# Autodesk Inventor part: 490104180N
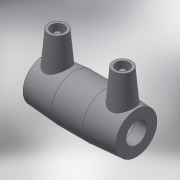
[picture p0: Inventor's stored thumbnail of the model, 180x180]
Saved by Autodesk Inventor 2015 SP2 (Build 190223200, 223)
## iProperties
Created: 2017-06
Part Number: 490104180N
Material: Generic
Description: PLASSON COUPLER 180-180
Document SubType Name: Modeling
Designer: KIM
Mass: 55.0731 g
Surface Area: 148.067 cm^2
Volume: 55.0731 cm^3
Density: 1 g/cm^3
Appearance: Default
Author: KIM
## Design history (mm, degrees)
derived "490104.ipt"
feature "Solid1::490104.ipt"
tag "TaggingFeature1"
body "Solid1"
other parameters: "d0" = 212, "d2" = 218, "d3" = 105, "d4" = 70.66667, "d5" = 196.2, "d6" = 171, "d8" = 168 deg, "d10" = 42, "d11" = 14, "d13" = 212, "d14" = 17.6296, "d15" = 105, "d16" = 105, "d17" = 171, "d19" = 3.52592, "d20" = 168 deg, "d22" = 204.92, "d23" = 218, "d24" = 198.7724, "d25" = 135 deg, "d26" = 106, "d27" = 135 deg, "d29" = 116, "d30" = 14, "d31" = 74.2, "d34" = 5 deg, "d35" = 15, "d39" = 5 deg, "d41" = 4, "d42" = 14, "d43" = 0, "d45" = 4, "d46" = 14, "d47" = 0, "d48" = 3, "d49" = 0, "d50" = 3, "d51" = 0, "d52" = 30.45, "d53" = 7.6125, "L_" = 212, "L_1" = 105, "D_" = 218, "A_" = 116, "d_2" = 12
